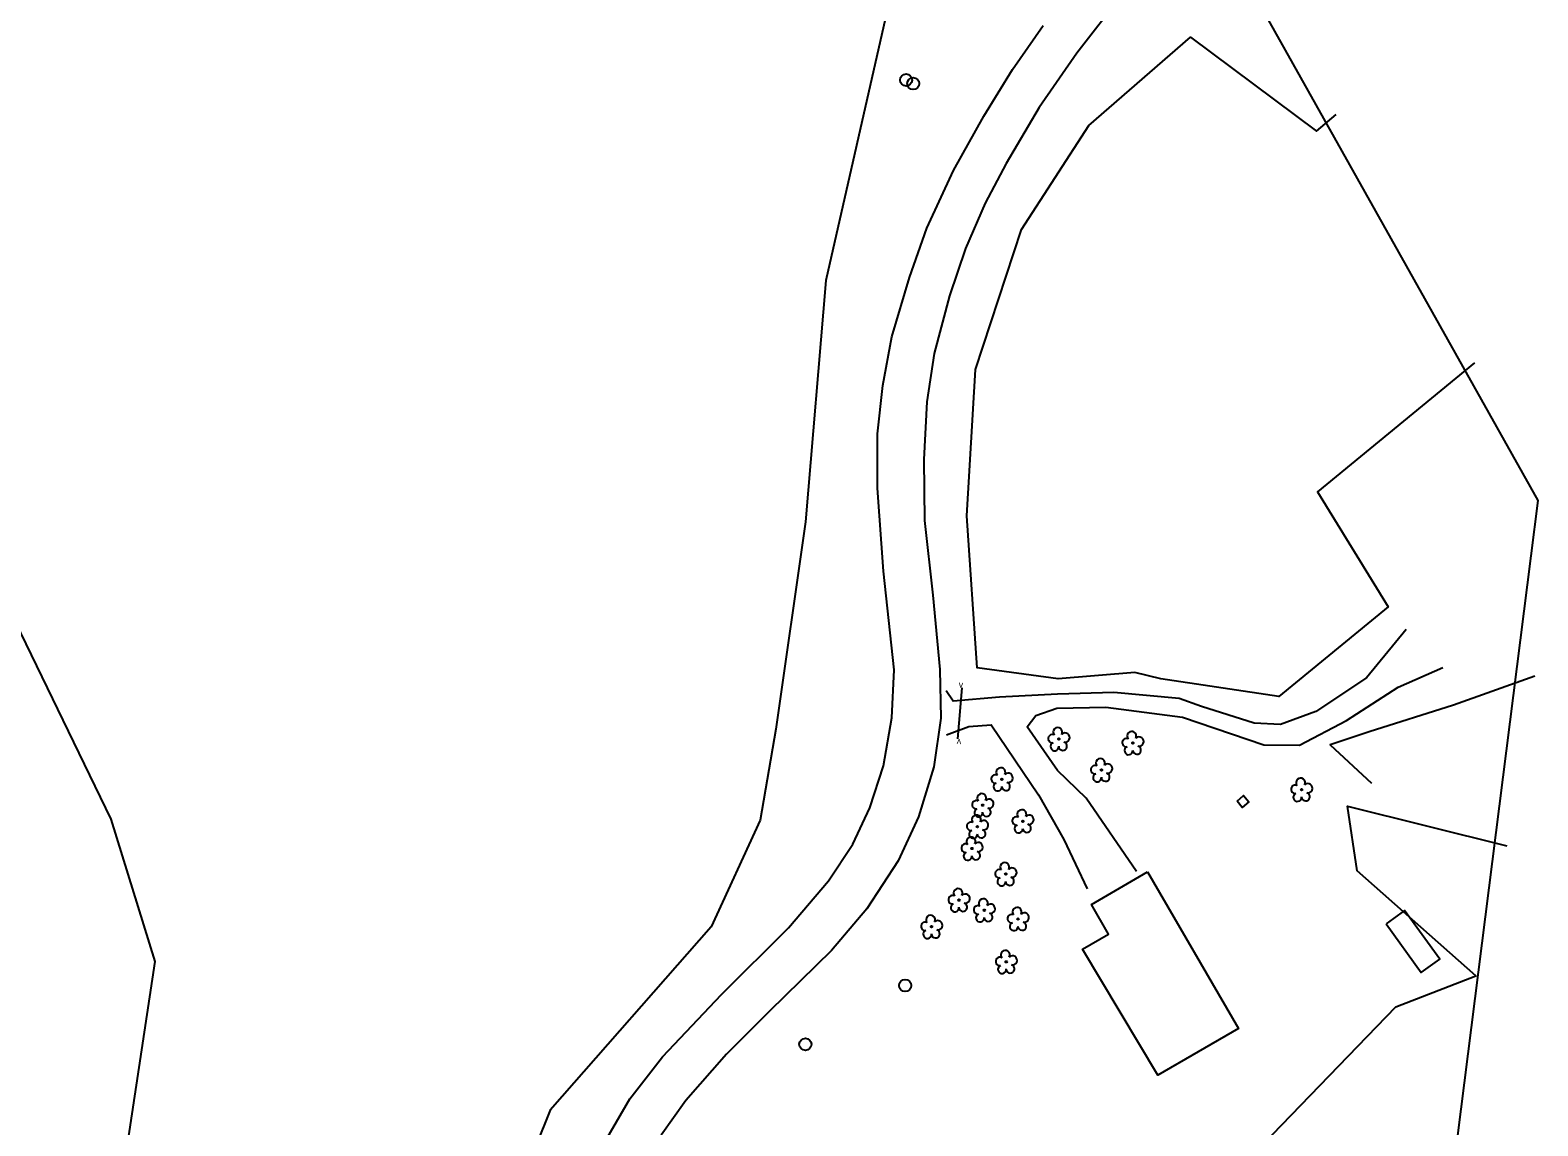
# Model space of a CAD drawing. Extents: x 1380524 to 1382335, y 594765 to 596944.
# Drawn here: x 1381533 to 1382148, y 596218 to 596665 of the extents above; entities that cross this region are included whole.
import ezdxf

# ---------------------------------------------------------------- set-up
doc = ezdxf.new("R2010")
doc.units = 0
for name, color, linetype in [('DTM Contours Major Text', 7, 'Continuous'), ('Prop Drainage Ditch Base Lines', 7, 'Continuous'), ('Prop Drainage Structure Box Number Symbol CELL', 7, 'Continuous'), ('Prop Drainage Structure Pipe Elbow CELL', 7, 'Continuous'), ('Prop Drainage Structure Pipe Elbow Label', 7, 'Continuous'), ('Prop Earthen Structure Cut Ditch Special Detail Label', 7, 'Continuous'), ('Prop Earthen Structure Ditch Flow Line', 7, 'Continuous'), ('Prop Earthen Structure V Ditch Lateral Detail Label', 7, 'Continuous'), ('Prop Erosion Rip Rap At Embankment Detail CELL', 7, 'Continuous')]:
    doc.layers.add(name, color=color, linetype=linetype)

# ---------------------------------------------------------------- blocks, each defined once
blk = doc.blocks.new('EXIST UTILITIES OTHER POLE')
at = {"layer": 'DTM Contours Major Text'}
blk.add_circle((0, 0), 0.0493, dxfattribs=at)
blk = doc.blocks.new('EXIST VEGETATION TREE')
at = {"layer": 'Prop Erosion Rip Rap At Embankment Detail CELL'}
blk.add_line((0, 0), (0, 0), dxfattribs=at)
blk.add_circle((0, 0), 0.00652, dxfattribs=at)
for centre, radius, start, end in [((-0.052, 0.003), 0.0345, 62.6636, 279.3457), ((-0.008, 0.057), 0.0371, 330.1651, 219.7134), ((0.051, 0.012), 0.038, 257.1011, 134.1999), ((-0.034, -0.062), 0.0338, 111.5671, 6.231), ((0.033, -0.058), 0.034, 181.2822, 74.56)]:
    blk.add_arc(centre, radius, start, end, dxfattribs=at)

msp = doc.modelspace()

# ---------------------------------------------------------------- linework, layer by layer
at = {"layer": 'Prop Drainage Ditch Base Lines'}
for points in [[(1382025.68, 596350.5), (1382028.24, 596352.8), (1382030.42, 596350.27), (1382027.63, 596347.97)], [(1381989.07, 596321.62), (1382026.24, 596257.67), (1381993.27, 596238.6), (1381962.49, 596290.15), (1381973.13, 596296.24), (1381966.08, 596308.32)], [(1382086.45, 596300.38), (1382100.84, 596280.6), (1382108.34, 596286.05), (1382093.94, 596305.84)]]:
    msp.add_lwpolyline(points, close=True, dxfattribs=at)
at = {"layer": 'Prop Drainage Structure Box Number Symbol CELL'}
msp.add_lwpolyline([(1382083.99, 595964.39), (1380966.64, 596251.47), (1381106.82, 596554.99), (1381897.61, 596920.15), (1382148.43, 596473.2)], close=True, dxfattribs=at)
at = {"layer": 'Prop Drainage Structure Pipe Elbow CELL'}
for points in [[(1382094.65, 596420.66), (1382078.44, 596400.82), (1382057.72, 596387.15), (1382043.31, 596381.84), (1382032.52, 596382.38), (1382011.01, 596389.12), (1382001.93, 596392.44), (1381975.22, 596394.94), (1381952.22, 596394.16), (1381928.56, 596392.98), (1381909.65, 596391.29), (1381906.85, 596395.51)], [(1381984.48, 596321.75), (1381964.01, 596351.79), (1381952.22, 596363.05), (1381939.85, 596380.85), (1381943.42, 596385.52), (1381952.02, 596388.43), (1381972.01, 596388.89), (1382003.31, 596384.76), (1382036.58, 596373.45), (1382051.05, 596373.36), (1382070.33, 596383.42), (1382091.43, 596397.11), (1382109.64, 596405.05)], [(1381906.97, 596377.57), (1381916.1, 596381.03), (1381925.19, 596381.65), (1381944.51, 596353.1), (1381954.82, 596334.8), (1381964.32, 596314.66)]]:
    msp.add_lwpolyline(points, dxfattribs=at)
at = {"layer": 'Prop Drainage Structure Pipe Elbow Label'}
msp.add_lwpolyline([(1381911.52, 596375.93), (1381913.34, 596396.8)], dxfattribs=at)
at = {"layer": 'Prop Earthen Structure Cut Ditch Special Detail Label'}
for points in [[(1381993.97, 596746.39), (1381926.82, 596678.09), (1381882.73, 596673.31), (1381857.71, 596563.06), (1381849.31, 596464.5), (1381837.19, 596379.89), (1381830.78, 596342.77), (1381810.83, 596299.24), (1381745.1, 596224.39), (1381733.09, 596194.6), (1381689.78, 596209.04), (1381619.47, 596192.74), (1381567.86, 596179.57), (1381583.81, 596285.11), (1381565.74, 596343.12), (1381520.02, 596437.2), (1381483.63, 596516.56), (1381436.21, 596610.27), (1381402.81, 596651.16), (1381345.44, 596643.18), (1381336.65, 596668.79)], [(1382122.58, 596529.43), (1382058.39, 596476.79), (1382087.3, 596429.81), (1382042.68, 596393.2), (1381994.44, 596400.39), (1381983.79, 596403.01), (1381952.53, 596400.45), (1381919.47, 596404.89), (1381915.21, 596466.94), (1381918.78, 596526.79), (1381937.6, 596583.87), (1381965.04, 596626.29), (1382006.59, 596662.45), (1382058.06, 596624.01), (1382066.08, 596630.8)], [(1382092.39, 595992.13), (1382082.77, 596096.76), (1382064.27, 596111.84), (1382028.39, 596202.28), (1382090.44, 596266.51), (1382123.08, 596279.15), (1382074.65, 596322.1), (1382070.72, 596348.45), (1382135.72, 596332.26)]]:
    msp.add_lwpolyline(points, dxfattribs=at)
at = {"layer": 'Prop Earthen Structure Ditch Flow Line'}
for points in [[(1381978.82, 596680.01), (1381960.19, 596655.9), (1381944.84, 596633.72), (1381931.27, 596610.87), (1381922.66, 596594.58), (1381914.62, 596576.1), (1381908.16, 596556.8), (1381901.89, 596533.22), (1381898.91, 596513.48), (1381897.7, 596490.03), (1381897.94, 596465.1), (1381901.29, 596434.57), (1381904.17, 596404.26), (1381904.61, 596384.44), (1381901.78, 596364.47), (1381895.43, 596344.16), (1381887.13, 596326.09), (1381874.43, 596306.61), (1381860.02, 596289.52), (1381834.63, 596264.83), (1381817.04, 596247.27), (1381800.53, 596228.26), (1381790.43, 596214.19)], [(1381768.2, 596212.74), (1381777.61, 596229.03), (1381790.97, 596246.17), (1381815.07, 596271.57), (1381842.36, 596298.81), (1381858.8, 596318.03), (1381868.69, 596332.93), (1381875.66, 596347.8), (1381881.24, 596364.92), (1381884.61, 596384.48), (1381885.51, 596404.12), (1381881.26, 596444.37), (1381878.71, 596478.27), (1381878.73, 596500.51), (1381880.87, 596520.21), (1381884.66, 596540.09), (1381891.75, 596564.26), (1381898.94, 596584.44), (1381909.84, 596607.94), (1381922.17, 596630.22), (1381933.85, 596649.2), (1381946.46, 596667.2)]]:
    msp.add_lwpolyline(points, dxfattribs=at)
at = {"layer": 'Prop Earthen Structure V Ditch Lateral Detail Label'}
msp.add_lwpolyline([(1382147.24, 596401.51), (1382114.02, 596389.68), (1382079.57, 596378.88), (1382063.67, 596373.45), (1382080.56, 596357.9)], dxfattribs=at)

# ---------------------------------------------------------------- block references
at = {"layer": 'DTM Contours Major Text', "xscale": 50, "yscale": 50}
for p in [(1381890.41, 596644.92), (1381893.35, 596643.45), (1381890.03, 596275.28), (1381849.29, 596251.25)]:
    msp.add_blockref('EXIST UTILITIES OTHER POLE', p, dxfattribs=at)
at = {"layer": 'Prop Erosion Rip Rap At Embankment Detail CELL', "xscale": 50, "yscale": 50}
for p in [(1381952.79, 596375.86), (1381983.02, 596374.26), (1381929.53, 596359.45), (1381970.21, 596363.22), (1382051.95, 596355.21), (1381921.7, 596348.89), (1381919.55, 596340.13), (1381938.1, 596342.32), (1381917.31, 596331.18), (1381931.14, 596320.75), (1381912.03, 596310.12), (1381922.35, 596306), (1381900.82, 596299.26), (1381936.16, 596302.43), (1381931.32, 596284.92)]:
    msp.add_blockref('EXIST VEGETATION TREE', p, dxfattribs=at)

# ---------------------------------------------------------------- texts
at = {"layer": 'Prop Drainage Structure Pipe Elbow Label'}
for rotation, p in [(355.24664, (1381911.85, 596396.92)), (174.76493, (1381913.02, 596375.8))]:
    msp.add_text('v', height=2.65, rotation=rotation, dxfattribs=at).set_placement(p)

doc.saveas('drawing.dxf')
